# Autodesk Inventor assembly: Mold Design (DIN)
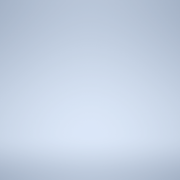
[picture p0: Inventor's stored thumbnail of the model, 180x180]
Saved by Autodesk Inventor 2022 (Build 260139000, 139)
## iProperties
Created: 2002-07
Part Number: Mold Design (DIN)
Document SubType Name: Assembly
Control State: 0
Master: False
Checked Out: False
Shininess: 64.0
Length Units: 11269
Angle Units: 11279
Time Units: 11290
Mass Units: 11283
Length Display Precision: 3
Angle Display Precision: 2
Compacted: True
Density: 0.0
Volumn: 0.0
Area: 0.0
PropertySet Name: Model Information
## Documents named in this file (1)
- C:\Users\ENU\Desktop\New folder for ita\Mold Design (DIN).iam
